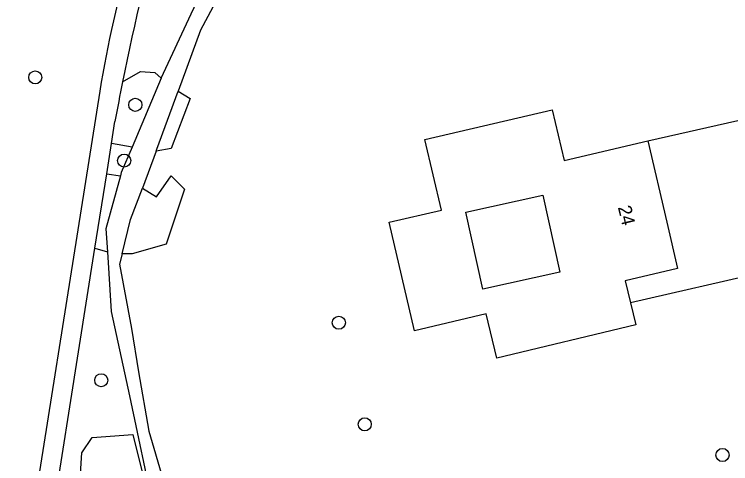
# Model space of a CAD drawing. Extents: x 156664 to 157568, y 383571 to 384421.
# Drawn here: x 156787.1 to 156840.7, y 384097.1 to 384130.7 of the extents above; entities that cross this region are included whole.
import ezdxf

# ---------------------------------------------------------------- set-up
doc = ezdxf.new("R2010")
doc.units = 0
for name, color, linetype in [('IMGEO_Boom', 7, 'Continuous'), ('IMGEO_Groenvoorziening', 7, 'Continuous'), ('IMGEO_Pand', 7, 'Continuous'), ('IMGEO_Pand_nummerreeks', 7, 'Continuous'), ('IMGEO_Voetpad_halfverhard', 7, 'Continuous'), ('IMGEO_Waterloop', 7, 'Continuous')]:
    doc.layers.add(name, color=color, linetype=linetype)

msp = doc.modelspace()

# ---------------------------------------------------------------- linework, layer by layer
at = {"layer": 'IMGEO_Boom'}
for centre in [(156788.702, 384125.983), (156796.179, 384123.934), (156795.347, 384119.762), (156811.387, 384107.653), (156793.635, 384103.352), (156813.319, 384100.061), (156840.046, 384097.767)]:
    msp.add_circle(centre, 0.489, dxfattribs=at)
at = {"layer": 'IMGEO_Groenvoorziening'}
for points in [[(156795.228, 384125.646), (156796.555, 384126.409), (156797.643, 384126.348), (156798.107, 384125.917)], [(156799.383, 384124.962), (156800.282, 384124.413), (156798.865, 384120.675), (156797.742, 384120.472)], [(156834.464, 384121.23), (156841.185, 384122.765)], [(156795.941, 384120.78), (156794.395, 384121.039)], [(156794.04, 384118.787), (156795.067, 384118.622)], [(156796.705, 384117.706), (156797.754, 384117.059), (156798.861, 384118.631), (156799.862, 384117.621), (156798.479, 384113.529), (156795.933, 384112.799), (156795.2, 384112.806)], [(156793.162, 384113.21), (156794.091, 384112.958)], [(156843.173, 384111.435), (156833.179, 384109.127)], [(156795.202, 384083.747), (156793.249, 384087.84), (156791.845, 384092.413), (156792.18, 384097.92), (156792.947, 384099.078), (156795.999, 384099.308), (156798.659, 384088.588), (156800.195, 384081.323), (156797.528, 384080.37), (156796.446, 384081.313), (156795.202, 384083.747)]]:
    msp.add_lwpolyline(points, dxfattribs=at)
at = {"layer": 'IMGEO_Pand'}
for points in [[(156833.179, 384109.127), (156833.569, 384107.488), (156823.18, 384105.014), (156822.392, 384108.322), (156817.042, 384107.048), (156815.141, 384115.16), (156819.046, 384116.071), (156817.816, 384121.34), (156827.334, 384123.561), (156828.229, 384119.777), (156834.464, 384121.23)], [(156834.464, 384121.23), (156835.881, 384115.158), (156836.688, 384111.699), (156832.783, 384110.788), (156833.179, 384109.127)], [(156822.151, 384110.155), (156820.878, 384115.909), (156826.632, 384117.181), (156827.904, 384111.428), (156822.151, 384110.155)]]:
    msp.add_lwpolyline(points, dxfattribs=at)
at = {"layer": 'IMGEO_Voetpad_halfverhard'}
for points in [[(156793.525, 384124.96), (156787.14, 384084.599)], [(156794.395, 384121.039), (156794.656, 384122.696)], [(156794.04, 384118.787), (156794.395, 384121.039)], [(156793.162, 384113.21), (156794.04, 384118.787)], [(156788.856, 384085.869), (156793.162, 384113.21)]]:
    msp.add_lwpolyline(points, dxfattribs=at)
for centre, radius, start, end in [((156990.865, 384086.149), 199.584, 160.75765, 168.58605), ((156888.14, 384109.263), 95.909, 164.20283, 170.57996), ((157012.254, 384082.035), 221.365, 168.63773, 169.4155)]:
    msp.add_arc(centre, radius, start, end, dxfattribs=at)
at = {"layer": 'IMGEO_Waterloop'}
for points in [[(156803.52, 384134.378), (156803.451, 384133.987), (156801.041, 384129.502), (156799.383, 384124.962)], [(156798.107, 384125.917), (156800.34, 384130.718), (156801.456, 384133.079)], [(156798.107, 384125.917), (156795.941, 384120.78)], [(156797.742, 384120.472), (156797.795, 384120.614), (156799.383, 384124.962)], [(156795.941, 384120.78), (156795.133, 384118.863), (156795.067, 384118.622)], [(156797.742, 384120.472), (156796.705, 384117.706)], [(156795.067, 384118.622), (156793.981, 384114.672), (156794.091, 384112.958)], [(156795.2, 384112.806), (156795.83, 384115.373), (156796.705, 384117.706)], [(156794.091, 384112.958), (156794.376, 384108.502), (156795.744, 384102.185), (156797.554, 384093.567), (156799.117, 384087.479), (156800.993, 384080.92), (156802.061, 384081.48)], [(156795.2, 384112.806), (156795.008, 384112.022), (156795.883, 384107.208), (156796.413, 384103.973), (156797.184, 384099.542), (156799.397, 384092.002), (156802.061, 384081.48)]]:
    msp.add_lwpolyline(points, dxfattribs=at)

# ---------------------------------------------------------------- texts
at = {"layer": 'IMGEO_Pand_nummerreeks'}
msp.add_text('24', height=1, rotation=283.6229, dxfattribs=at).set_placement((156832.225, 384116.282))

doc.saveas('drawing.dxf')
